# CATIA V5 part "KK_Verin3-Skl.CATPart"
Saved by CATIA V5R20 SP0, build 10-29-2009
Part number: Verin3-Skl
Bounding box of the stored display mesh (mm): x 63.395 to 99.999, y -13.265 to 0.34, z 0 to 100
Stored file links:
  G:\Khaled_CFAO_2011\ST2M\ST2M_GR1\msallin\Khaled\Version_Finale\KK_Verin3-Skl.CATPart
  C:\Users\Mathieu\Desktop\Think Motion\JOUG-MELEE2.CATProduct
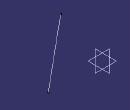
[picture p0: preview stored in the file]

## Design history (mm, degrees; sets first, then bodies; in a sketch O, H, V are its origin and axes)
Set1
  Point1: linked copy from another document
  Point2: linked copy from another document
Set2
  Line1: type PtPt, FirstPoint Point1, SecondPoint Point2
Body1 (main body)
